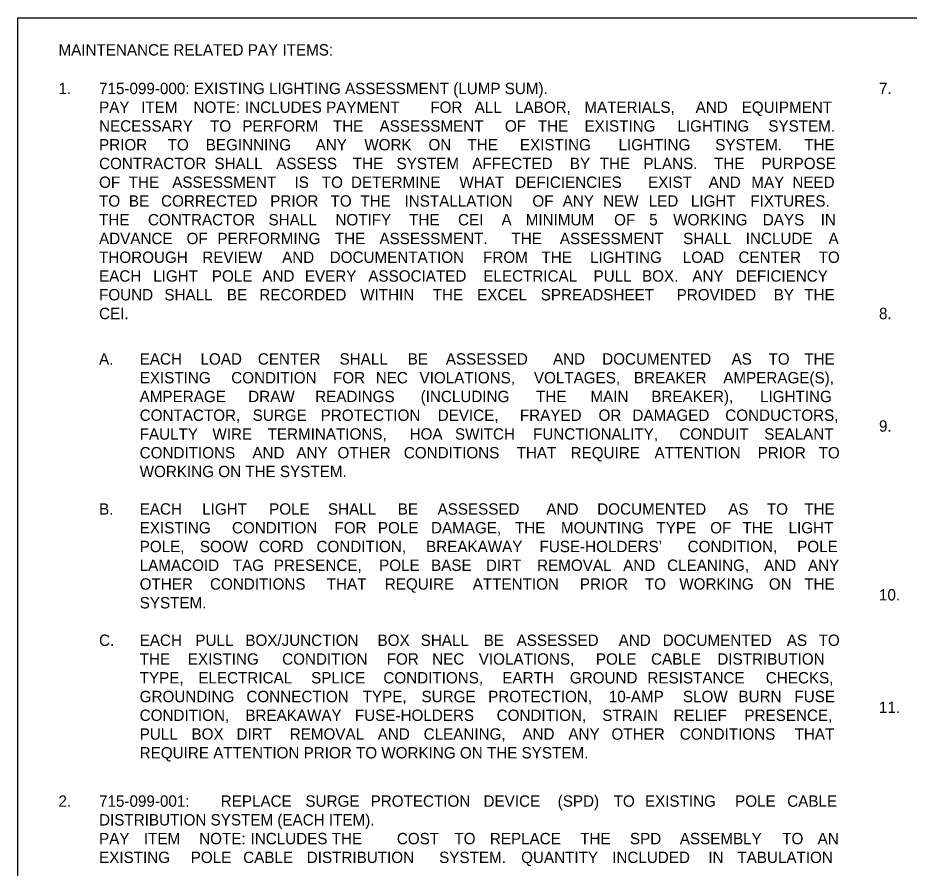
# Model space of a CAD drawing. Extents: x -55 to 2471539, y -90 to 3608906.
# Drawn here: x 0 to 549, y 436 to 960 of the extents above; entities that cross this region are included whole.
import ezdxf

# ---------------------------------------------------------------- set-up
doc = ezdxf.new("R2010")
doc.units = 0
doc.layers.add('NonPlottingEle_dp', color=7, linetype='Continuous')
doc.layers.add('TextNotes', color=7, linetype='Continuous')

msp = doc.modelspace()

# ---------------------------------------------------------------- linework, layer by layer
at = {"layer": 'NonPlottingEle_dp'}
msp.add_lwpolyline([(0, 0), (0, 960), (1540, 960), (1540, 0)], dxfattribs=at)

# ---------------------------------------------------------------- texts
at = {"layer": 'TextNotes'}
for s, p in [('MAINTENANCE RELATED PAY ITEMS:', (25.02, 936.77)), ('1.', (25.02, 913)), ('715-099-000: EXISTING LIGHTING ASSESSMENT (LUMP SUM).', (50, 913)), ('7.', (530.02, 913)), ('PAY ', (50, 901.45)), ('ITEM ', (75.88, 901.45)), ('NOTE:', (108.15, 901.45)), (' INCLUDES PAYMENT ', (137.18, 901.45)), ('FOR ', (253.89, 901.45)), ('ALL ', (281.18, 901.45)), ('LABOR, ', (306.01, 901.45)), ('MATERIALS, ', (348.68, 901.45)), ('AND ', (417.16, 901.45)), ('EQUIPMENT ', (445.52, 901.45)), ('NECESSARY ', (50, 889.9)), ('TO ', (118.3, 889.9)), ('PERFORM ', (138.19, 889.9)), ('THE ', (193.91, 889.9)), ('ASSESSMENT ', (222.64, 889.9)), ('OF ', (299.82, 889.9)), ('THE ', (320.06, 889.9)), ('EXISTING ', (348.79, 889.9)), ('LIGHTING ', (405.96, 889.9)), ('SYSTEM. ', (461.91, 889.9)), ('PRIOR ', (50, 878.35)), ('TO ', (92.22, 878.35)), ('BEGINNING ', (115.67, 878.35)), ('ANY ', (183.28, 878.35)), ('WORK ', (213.26, 878.35)), ('ON ', (252.72, 878.35)), ('THE ', (276.73, 878.35)), ('EXISTING ', (309.01, 878.35)), ('LIGHTING ', (369.73, 878.35)), ('SYSTEM. ', (429.24, 878.35)), ('THE ', (484.03, 878.35)), ('CONTRACTOR ', (50, 866.8)), ('SHALL ', (121.03, 866.8)), ('ASSESS ', (159.01, 866.8)), ('THE ', (206.18, 866.8)), ('SYSTEM ', (233.08, 866.8)), ('AFFECTED ', (279.72, 866.8)), ('BY ', (339.78, 866.8)), ('THE ', (358.1, 866.8)), ('PLANS. ', (384.99, 866.8)), (' THE ', (425.91, 866.8)), ('PURPOSE ', (457.71, 866.8)), ('OF ', (50, 855.25)), ('THE ', (68.28, 855.25)), ('ASSESSMENT ', (95.05, 855.25)), ('IS ', (170.28, 855.25)), ('TO ', (187.08, 855.25)), ('DETERMINE ', (205.02, 855.25)), ('WHAT ', (271.75, 855.25)), ('DEFICIENCIES ', (306.15, 855.25)), ('EXIST ', (387.88, 855.25)), ('AND ', (425.21, 855.25)), ('MAY ', (451.44, 855.25)), ('NEED ', (476.71, 855.25)), ('TO ', (50, 843.7)), ('BE ', (68.35, 843.7)), ('CORRECTED ', (88.17, 843.7)), ('PRIOR ', (155.35, 843.7)), ('TO ', (192.47, 843.7)), ('THE ', (210.82, 843.7)), ('INSTALLATION ', (238, 843.7)), ('OF ', (316.67, 843.7)), ('ANY ', (335.36, 843.7)), ('NEW ', (360.25, 843.7)), ('LED ', (388.28, 843.7)), ('LIGHT ', (414.26, 843.7)), ('FIXTURES. ', (450.8, 843.7)), ('THE ', (50, 832.15)), ('CONTRACTOR ', (80.09, 832.15)), ('SHALL ', (154.31, 832.15)), ('NOTIFY ', (195.48, 832.15)), ('THE ', (240.85, 832.15)), ('CEI ', (270.94, 832.15)), ('A ', (297.68, 832.15)), ('MINIMUM ', (312.6, 832.15)), ('OF ', (366.99, 832.15)), ('5 ', (388.59, 832.15)), ('WORKING ', (403.38, 832.15)), ('DAYS ', (458.52, 832.15)), ('IN ', (494.14, 832.15)), ('ADVANCE ', (50, 820.6)), ('OF ', (103.85, 820.6)), ('PERFORMING ', (122.81, 820.6)), ('THE ', (195.12, 820.6)), ('ASSESSMENT. ', (222.56, 820.6)), (' THE ', (301.23, 820.6)), ('ASSESSMENT ', (333.58, 820.6)), ('SHALL ', (409.49, 820.6)), ('INCLUDE ', (448.02, 820.6)), ('A ', (498.99, 820.6)), ('THOROUGH ', (50, 809.05)), ('REVIEW ', (113.52, 809.05)), ('AND ', (162.66, 809.05)), ('DOCUMENTATION ', (191.97, 809.05)), ('FROM ', (286.37, 809.05)), ('THE ', (322.33, 809.05)), ('LIGHTING ', (352.19, 809.05)), ('LOAD ', (409.27, 809.05)), ('CENTER ', (443.56, 809.05)), ('TO ', (492.86, 809.05)), ('EACH ', (50, 797.5)), ('LIGHT ', (83.33, 797.5)), ('POLE ', (119.41, 797.5)), ('AND ', (150.47, 797.5)), ('EVERY ', (176.66, 797.5)), ('ASSOCIATED ', (215.72, 797.5)), ('ELECTRICAL ', (286.51, 797.5)), ('PULL ', (354.34, 797.5)), ('BOX. ', (384.16, 797.5)), (' ANY ', (412.54, 797.5)), ('DEFICIENCY ', (441.88, 797.5)), ('FOUND ', (50, 785.95)), ('SHALL ', (90.2, 785.95)), ('BE ', (128.64, 785.95)), ('RECORDED ', (148.63, 785.95)), ('WITHIN ', (210.74, 785.95)), ('THE ', (255.31, 785.95)), ('EXCEL ', (282.67, 785.95)), ('SPREADSHEET ', (321.85, 785.95)), ('PROVIDED ', (405.48, 785.95)), ('BY ', (465.24, 785.95)), ('THE ', (484.03, 785.95)), ('CEI. ', (50, 774.4)), ('8.', (530.02, 774.4)), ('A.', (50, 746.4)), ('EACH ', (75, 746.4)), ('LOAD ', (112.45, 746.4)), ('CENTER ', (147.73, 746.4)), ('SHALL ', (198.02, 746.4)), ('BE ', (239.94, 746.4)), ('ASSESSED ', (263.42, 746.4)), ('AND ', (329.37, 746.4)), ('DOCUMENTED ', (359.67, 746.4)), ('AS ', (439.26, 746.4)), ('TO ', (462.02, 746.4)), ('THE ', (484.03, 746.4)), ('EXISTING ', (75, 734.85)), ('CONDITION ', (131.35, 734.85)), ('FOR ', (193.98, 734.85)), ('NEC ', (220.28, 734.85)), ('VIOLATIONS, ', (247.24, 734.85)), ('VOLTAGES, ', (317.62, 734.85)), ('BREAKER ', (379.17, 734.85)), ('AMPERAGE(S), ', (434.17, 734.85)), ('AMPERAGE ', (75, 723.3)), ('DRAW ', (141.82, 723.3)), ('READINGS ', (183.01, 723.3)), ('(INCLUDING ', (247.92, 723.3)), ('THE ', (318.98, 723.3)), ('MAIN ', (352.4, 723.3)), ('BREAKER), ', (389.86, 723.3)), ('LIGHTING ', (456.79, 723.3)), ('CONTACTOR, ', (75, 711.75)), ('SURGE ', (144.54, 711.75)), ('PROTECTION ', (186.39, 711.75)), ('DEVICE, ', (258.43, 711.75)), ('FRAYED ', (309.01, 711.75)), ('OR ', (357.41, 711.75)), ('DAMAGED ', (378.3, 711.75)), ('CONDUCTORS, ', (435.41, 711.75)), ('9.', (530.02, 705.1)), ('FAULTY ', (75, 700.2)), ('WIRE ', (119.76, 700.2)), ('TERMINATIONS, ', (153.73, 700.2)), ('HOA ', (241.14, 700.2)), ('SWITCH ', (269.06, 700.2)), ('FUNCTIONALITY, ', (317.1, 700.2)), ('CONDUIT ', (407.16, 700.2)), ('SEALANT ', (459.4, 700.2)), ('CONDITIONS ', (75, 688.65)), ('AND ', (144.39, 688.65)), ('ANY ', (171.44, 688.65)), ('OTHER ', (196.74, 688.65)), ('CONDITIONS ', (237.58, 688.65)), ('THAT ', (306.97, 688.65)), ('REQUIRE ', (340.22, 688.65)), ('ATTENTION ', (391.86, 688.65)), ('PRIOR ', (455.33, 688.65)), ('TO ', (492.86, 688.65)), ('WORKING ON THE SYSTEM.', (75, 677.1)), ('B.', (50, 654)), ('EACH ', (75, 654)), ('LIGHT ', (113.46, 654)), ('POLE ', (154.68, 654)), ('SHALL ', (190.88, 654)), ('BE ', (233.82, 654)), ('ASSESSED ', (258.32, 654)), ('AND ', (325.29, 654)), ('DOCUMENTED ', (356.62, 654)), ('AS ', (437.22, 654)), ('TO ', (461, 654)), ('THE ', (484.03, 654)), ('EXISTING ', (75, 642.45)), ('CONDITION ', (131.8, 642.45)), ('FOR ', (194.87, 642.45)), ('POLE ', (221.61, 642.45)), ('DAMAGE, ', (254.31, 642.45)), ('THE ', (305.94, 642.45)), ('MOUNTING ', (334.29, 642.45)), ('TYPE ', (393.06, 642.45)), ('OF ', (426.15, 642.45)), ('THE ', (446.01, 642.45)), ('LIGHT ', (474.37, 642.45)), ('POLE, ', (75, 630.9)), ('SOOW ', (112.04, 630.9)), ('CORD ', (148.28, 630.9)), ('CONDITION, ', (183.83, 630.9)), ('BREAKAWAY ', (251.25, 630.9)), ('FUSE-HOLDERS’ ', (321.09, 630.9)), ('CONDITION, ', (412.27, 630.9)), ('POLE ', (479.69, 630.9)), ('LAMACOID ', (75, 619.35)), ('TAG ', (132.3, 619.35)), ('PRESENCE, ', (157.55, 619.35)), ('POLE ', (222.38, 619.35)), ('BASE ', (254.34, 619.35)), ('DIRT ', (288.1, 619.35)), ('REMOVAL ', (319.61, 619.35)), ('AND ', (372.56, 619.35)), ('CLEANING, ', (399.65, 619.35)), ('AND ', (459.23, 619.35)), ('ANY ', (486.32, 619.35)), ('OTHER ', (75, 607.8)), ('CONDITIONS ', (118.3, 607.8)), ('THAT ', (190.16, 607.8)), ('REQUIRE ', (225.87, 607.8)), ('ATTENTION ', (279.98, 607.8)), ('PRIOR ', (345.91, 607.8)), ('TO ', (385.91, 607.8)), ('WORKING ', (407.13, 607.8)), ('ON ', (462.24, 607.8)), ('THE ', (484.03, 607.8)), ('10.', (530.02, 601.15)), ('SYSTEM.', (75, 596.25)), ('C.', (50, 573.15)), ('EACH ', (75, 573.15)), ('PULL ', (109.26, 573.15)), ('BOX/JUNCTION ', (140.01, 573.15)), ('BOX ', (221.42, 573.15)), ('SHALL ', (247.97, 573.15)), ('BE ', (286.71, 573.15)), ('ASSESSED ', (307, 573.15)), ('AND ', (369.77, 573.15)), ('DOCUMENTED ', (396.89, 573.15)), ('AS ', (473.28, 573.15)), ('TO ', (492.86, 573.15)), ('THE ', (75, 561.6)), ('EXISTING ', (104.62, 561.6)), ('CONDITION ', (162.68, 561.6)), ('FOR ', (227.02, 561.6)), ('NEC ', (255.03, 561.6)), ('VIOLATIONS, ', (283.7, 561.6)), ('POLE ', (355.79, 561.6)), ('CABLE ', (389.75, 561.6)), ('DISTRIBUTION ', (430.53, 561.6)), ('TYPE, ', (75, 550.05)), ('ELECTRICAL ', (111.11, 550.05)), ('SPLICE ', (180.53, 550.05)), ('CONDITIONS, ', (224.99, 550.05)), ('EARTH ', (298.17, 550.05)), ('GROUND ', (339.79, 550.05)), ('RESISTANCE ', (387.51, 550.05)), ('CHECKS, ', (460.38, 550.05)), ('GROUNDING ', (75, 538.5)), ('CONNECTION ', (140.7, 538.5)), ('TYPE, ', (212.25, 538.5)), ('SURGE ', (248.45, 538.5)), ('PROTECTION, ', (289.49, 538.5)), ('10-AMP ', (363.77, 538.5)), ('SLOW ', (409.35, 538.5)), ('BURN ', (443.53, 538.5)), ('FUSE ', (477.97, 538.5)), ('11.', (530.02, 531.85)), ('CONDITION, ', (75, 526.95)), ('BREAKAWAY ', (140.02, 526.95)), ('FUSE-HOLDERS ', (207.46, 526.95)), ('CONDITION, ', (294.7, 526.95)), ('STRAIN ', (359.72, 526.95)), ('RELIEF ', (403.6, 526.95)), ('PRESENCE, ', (447.21, 526.95)), ('PULL ', (75, 515.4)), ('BOX ', (106.91, 515.4)), ('DIRT ', (134.63, 515.4)), ('REMOVAL ', (167.35, 515.4)), ('AND ', (221.49, 515.4)), ('CLEANING, ', (249.78, 515.4)), ('AND ', (310.56, 515.4)), ('ANY ', (338.84, 515.4)), ('OTHER ', (365.37, 515.4)), ('CONDITIONS ', (407.45, 515.4)), ('THAT ', (478.07, 515.4)), ('REQUIRE ATTENTION PRIOR TO WORKING ON THE SYSTEM.', (75, 503.85)), ('2.', (25.02, 474.1)), ('715-099-001: ', (50, 474.1)), ('REPLACE ', (124.87, 474.1)), ('SURGE ', (177, 474.1)), ('PROTECTION ', (217.13, 474.1)), ('DEVICE ', (286.63, 474.1)), ('(SPD) ', (332.28, 474.1)), ('TO ', (366.71, 474.1)), ('EXISTING ', (385.96, 474.1)), ('POLE ', (441.48, 474.1)), ('CABLE ', (473.54, 474.1)), ('DISTRIBUTION SYSTEM (EACH ITEM).', (50, 462.55)), ('PAY ', (50, 451)), ('ITEM ', (77.61, 451)), ('NOTE:', (111.61, 451)), (' INCLUDES THE ', (140.64, 451)), ('COST ', (233.28, 451)), ('TO ', (268.71, 451)), ('REPLACE ', (290.51, 451)), ('THE ', (346.1, 451)), ('SPD ', (376.73, 451)), ('ASSEMBLY ', (407.41, 451)), ('TO ', (470.46, 451)), ('AN ', (492.25, 451)), ('EXISTING ', (50, 439.45)), ('POLE ', (106.41, 439.45)), ('CABLE ', (138.72, 439.45)), ('DISTRIBUTION ', (177.84, 439.45)), ('SYSTEM. ', (259.31, 439.45)), ('QUANTITY ', (309.78, 439.45)), ('INCLUDED ', (365.81, 439.45)), ('IN ', (425, 439.45)), ('TABULATION ', (442.86, 439.45))]:
    msp.add_text(s, height=7, dxfattribs=at).set_placement(p)

doc.saveas('drawing.dxf')
